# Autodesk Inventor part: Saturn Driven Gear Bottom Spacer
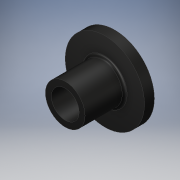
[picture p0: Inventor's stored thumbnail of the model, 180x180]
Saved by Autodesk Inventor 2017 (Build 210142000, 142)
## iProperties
Created: 2016-07
Part Number: Saturn Driven Gear Bottom Spacer
Material: Generic
Document SubType Name: Modeling
Designer: Stan
Density: 1 g/cm^3
Appearance: Glossy - Black
Author: Stan
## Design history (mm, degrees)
sketch "Sketch1"
  geometry: C1 r 12.7 at (0, 0); 1 further point
  constraints: 1 centre point, 1 coincident
  dimensions: "d0" = 25.4 diameter of C1
extrude "Extrusion1" new body sketch "Sketch1" distance "d1" = 3.175; taper "d2" = 0 deg
sketch "Sketch2"
  geometry: C1 r 6.35 at (0, 0); 1 further point
  constraints: 1 centre point, 1 coincident
  dimensions: "d3" = 12.7 diameter of C1
extrude "Extrusion2" join sketch "Sketch2" distance "d4" = 12.7; taper "d5" = 0 deg
sketch "Sketch3"
  geometry: C1 r 4.445 at (0, 0); 1 further point
  constraints: 1 centre point, 1 coincident
  dimensions: "d6" = 8.89 diameter of C1
extrude "Extrusion3" cut sketch "Sketch3" distance "d7" = 15.875; taper "d8" = 0 deg
fillet "Fillet1" dims "d9" = 0.79375
fillet "Fillet2" dims "d10" = 0.762
body "Solid1"
